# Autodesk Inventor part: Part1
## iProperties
Shininess: 64.0
Length Units: 11269
Angle Units: 11279
Time Units: 11290
Mass Units: 11283
Length Display Precision: 3
Angle Display Precision: 2
Compacted: True
Part Number: Part1
Document SubType Name: Modeling
Created: 2003-01
Designer: Owner
Density: 0.0
Volumn: 0.0
Area: 0.0
PropertySet Name: Model Information
Control State: 0
Master: False
Checked Out: False
Author: Owner
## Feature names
1. Extrusion1
2. Chamfer1
